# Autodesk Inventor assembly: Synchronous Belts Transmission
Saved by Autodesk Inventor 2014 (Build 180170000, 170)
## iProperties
Created: 2013-12
Part Number: Synchronous Belts Transmission
Document SubType Name: Assembly
Designer: Bram
ClientObjectVersion: 1
Author: Bram
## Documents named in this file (4)
- D:\gDrive\Google Drive\Hobby\3D Printer\3D printer\Inventor\PrinterAssambly\Design Accelerator\Synchronous Belts Transmission1.iam
- D:\gDrive\Google Drive\Hobby\3D Printer\3D printer\Inventor\PrinterAssambly\Design Accelerator\Synchronous Belt1.ipt
- D:\gDrive\Google Drive\Hobby\3D Printer\3D printer\Inventor\PrinterAssambly\Design Accelerator\Synchronous Pulley11.ipt
- D:\gDrive\Google Drive\Hobby\3D Printer\3D printer\Inventor\PrinterAssambly\Design Accelerator\Synchronous Pulley21.ipt
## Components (3 placed, 3 different names)
1. Synchronous Belt:1 — Flush:1, Flush:2
2. Synchronous Pulley1:1 — Flush:1, Rotation:1
3. Synchronous Pulley2:1 — Flush:2, Rotation:1
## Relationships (3: Flush 2, RelateRotation 1)
- Flush:1: Synchronous Belt:1 ↔ Synchronous Pulley1:1
- Flush:2: Synchronous Belt:1 ↔ Synchronous Pulley2:1
- Rotation:1 [RelateRotation]: Synchronous Pulley1:1 ↔ Synchronous Pulley2:1
